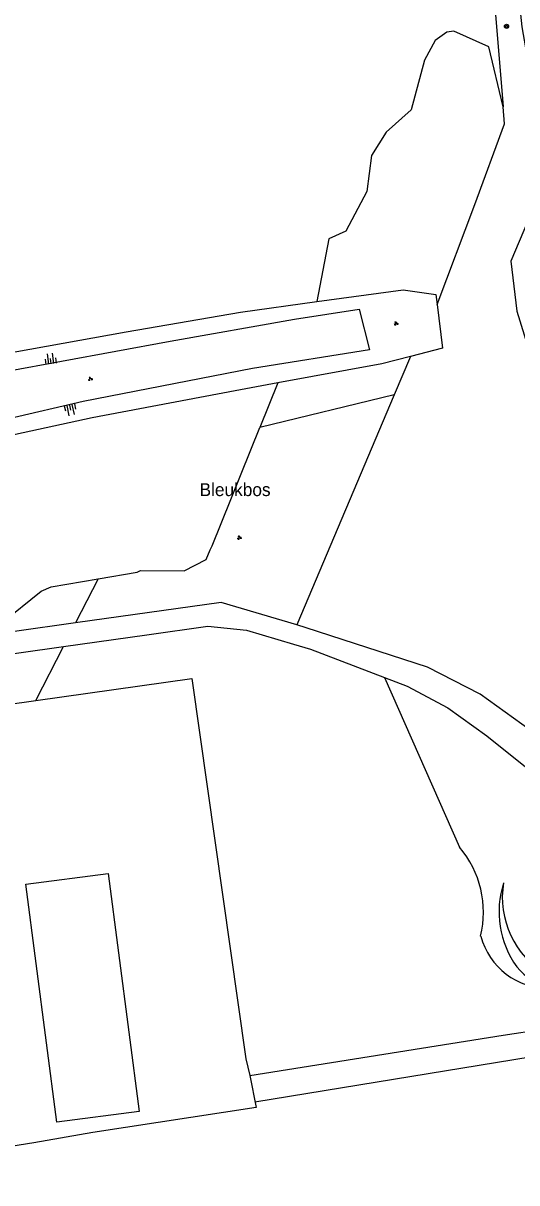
# Model space of a CAD drawing. Extents: x 125000 to 129004, y 397500 to 399008.
# Drawn here: x 126006.6 to 126102.2, y 397500 to 397724.5 of the extents above; entities that cross this region are included whole.
import ezdxf

# ---------------------------------------------------------------- set-up
doc = ezdxf.new("R2010")
doc.units = 0
for name, color, linetype in [('gg-afsc-lijn draadraster', 7, 'Continuous'), ('gg-anno-openbare ruimte label', 7, 'Continuous'), ('gg-knt-BGT kruinlijn', 7, 'Continuous'), ('gg-knt-bovenkant onderkant talud', 7, 'Continuous'), ('gg-knt-onverhard', 7, 'Continuous'), ('gt-bbg-plantopografie pand', 7, 'Continuous'), ('gt-grn-groengrens', 7, 'Continuous'), ('gt-symb-boom', 7, 'Continuous'), ('gt-symb-groenvak', 7, 'Continuous'), ('gt-symb-talud symbool', 7, 'Continuous'), ('gx-grn-maaiveld', 7, 'Continuous')]:
    doc.layers.add(name, color=color, linetype=linetype)

# ---------------------------------------------------------------- blocks, each defined once
blk = doc.blocks.new('gt0-BOOM')
at = {"layer": 'gt-symb-boom'}
for radius in [0.4, 0.2]:
    blk.add_circle((0, 0), radius, dxfattribs=at)
blk = doc.blocks.new('gt0-GRVAK')
at = {"layer": 'gt-symb-groenvak'}
for p, q in [((-0.11, 0.19), (-0.23, 0.24)), ((-0.18, 0.15), (0.09, 0.15)), ((-0.09, 0.21), (-0.16, 0.32)), ((-0.05, 0.21), (-0.05, 0.39)), ((0, 0.21), (0.06, 0.32)), ((0.01, 0.19), (0.13, 0.24)), ((0.26, -0.05), (0.2, 0.06)), ((0.3, -0.05), (0.3, 0.13)), ((0.35, -0.05), (0.41, 0.06)), ((-0.24, -0.23), (-0.36, -0.18)), ((-0.32, -0.26), (-0.05, -0.26)), ((-0.23, -0.21), (-0.29, -0.09)), ((-0.18, -0.2), (-0.18, -0.02)), ((-0.14, -0.21), (-0.07, -0.09)), ((-0.12, -0.23), (0, -0.18)), ((0.24, -0.07), (0.12, -0.02)), ((0.17, -0.11), (0.44, -0.11)), ((0.37, -0.07), (0.49, -0.02))]:
    blk.add_line(p, q, dxfattribs=at)
blk = doc.blocks.new('gt0-TALUD_1')
at = {"layer": 'gt-symb-talud symbool'}
for p, q in [((-1, -1), (-1, 0)), ((-0.5, -2), (-0.5, 0)), ((0, -1), (0, 0)), ((0.5, -2), (0.5, 0)), ((1, -1), (1, 0))]:
    blk.add_line(p, q, dxfattribs=at)

msp = doc.modelspace()

# ---------------------------------------------------------------- linework, layer by layer
at = {"layer": 'gg-afsc-lijn draadraster'}
msp.add_lwpolyline([(126051.46, 397515.7), (126198.71, 397539.74), (126267.59, 397550.89), (126278.2, 397500)], dxfattribs=at)
at = {"layer": 'gg-knt-BGT kruinlijn'}
msp.add_lwpolyline([(126073.67, 397661.32), (126051.03, 397657.69), (126018.21, 397651.29), (125989.35, 397644.55), (125967.38, 397640.9), (125969.88, 397652.16), (126003.49, 397657.14), (126035.06, 397662.99), (126059.15, 397667.23), (126071.66, 397669.17), (126073.67, 397661.32)], dxfattribs=at)
msp.add_arc((126116.64, 397555.22), 17.26, 170.3567, 239.7827, dxfattribs=at)
at = {"layer": 'gg-knt-bovenkant onderkant talud'}
for points in [[(126063.47, 397670.62), (126080.15, 397672.94), (126086.5, 397671.98), (126086.74, 397670.05)], [(125959.49, 397654.55), (125974.01, 397656.86), (125998.85, 397659.81), (126026.56, 397664.77), (126048.67, 397668.56), (126063.47, 397670.62)], [(126086.74, 397670.05), (126087.8, 397661.61), (126081.63, 397660.01)], [(126081.63, 397660.01), (126076.03, 397658.56), (126055.92, 397654.89)], [(126055.92, 397654.89), (126047.68, 397653.38), (126020, 397648.15), (125985.79, 397640.73), (125958.27, 397635.98), (125958.7, 397652.38)]]:
    msp.add_lwpolyline(points, dxfattribs=at)
for centre, radius, start, end in [((126117.1, 397552.49), 18.36, 162.1742, 215.642), ((126112.9, 397550.97), 14.11, 220.5741, 251.9124)]:
    msp.add_arc(centre, radius, start, end, dxfattribs=at)
at = {"layer": 'gg-knt-onverhard'}
for points in [[(126100, 397756.19), (126100.33, 397756.04), (126102.82, 397752.9), (126102.63, 397749.78), (126101.62, 397738.69), (126103.15, 397723.83), (126105.48, 397710.56), (126107.74, 397700.62), (126107.48, 397693.69), (126101.04, 397678.43), (126102.22, 397668.77), (126107.61, 397651.27), (126113.05, 397629.84), (126114.23, 397618.93), (126113.78, 397610.27), (126112.39, 397600.68), (126109.62, 397584.17), (126095.09, 397594.6), (126084.92, 397599.84), (126061.39, 397607.49), (126059.59, 397608.02)], [(126059.59, 397608.02), (126044.94, 397612.35), (126016.75, 397608.42)], [(126016.75, 397608.42), (126004.96, 397606.78), (125970.06, 397601.41), (125926.58, 397595.14)], [(126014.4, 397603.84), (126030.55, 397606.12), (126042.39, 397607.77), (126049.86, 397606.98), (126058.95, 397604.3)], [(125923.23, 397589.37), (125937.21, 397592.52), (125997.52, 397601.46), (126014.4, 397603.84)], [(126058.95, 397604.3), (126062.26, 397603.32), (126076.54, 397597.86)], [(126076.54, 397597.86), (126080.98, 397596.17), (126088.86, 397591.99), (126096.4, 397586.58), (126112.88, 397573.3), (126117.71, 397569.5), (126138.34, 397566.94), (126159.34, 397570.09), (126171, 397570.07), (126205.28, 397564.59)]]:
    msp.add_lwpolyline(points, dxfattribs=at)
at = {"layer": 'gt-bbg-plantopografie pand'}
msp.add_lwpolyline([(126007.15, 397557.8), (126023.07, 397559.88), (126029.06, 397513.81), (126013.15, 397511.74), (126007.15, 397557.8)], dxfattribs=at)
at = {"layer": 'gt-grn-groengrens'}
for p, q in [((126081.63, 397660.01), (126078.47, 397652.56)), ((126055.92, 397654.89), (126052.44, 397646.24)), ((126078.47, 397652.56), (126052.44, 397646.24)), ((126078.47, 397652.56), (126059.59, 397608.02)), ((126021.11, 397616.94), (126016.75, 397608.42)), ((126009.05, 397593.39), (126014.4, 397603.84)), ((126076.54, 397597.86), (126091.09, 397564.98))]:
    msp.add_line(p, q, dxfattribs=at)
for points in [[(126100, 397756.19), (126097.84, 397728.53), (126099.52, 397708.32)], [(126099.52, 397708.32), (126096.78, 397719.96), (126090.01, 397722.97), (126088.66, 397722.82), (126086.4, 397721.16), (126084.3, 397717.4), (126081.74, 397707.77), (126076.92, 397703.41), (126074.07, 397698.89), (126073.16, 397691.97), (126069.1, 397684.3), (126065.79, 397682.8), (126063.47, 397670.62)], [(126086.74, 397670.05), (126094.08, 397689.42), (126099.79, 397705.06), (126099.52, 397708.32)], [(126021.11, 397616.94), (126028.7, 397618.21), (126029.32, 397618.56), (126037.81, 397618.51), (126042.05, 397620.71), (126042.81, 397622.58), (126043.22, 397623.33), (126052.44, 397646.24)], [(125931.07, 397603.13), (125943.28, 397606.67), (125953.74, 397607.31), (125979.58, 397610.73), (125985.56, 397613.72), (125987.48, 397616.28), (125989.83, 397617.35), (125991.75, 397617.35), (125993.46, 397616.5), (125997.3, 397612.87), (125997.73, 397608.81), (126002.43, 397608.38), (126010.12, 397614.58), (126012.04, 397615.43), (126021.11, 397616.94)], [(125929.64, 397557.36), (125930.79, 397557.32), (125930.48, 397559.56), (125922.63, 397581.22), (126009.05, 397593.39)]]:
    msp.add_lwpolyline(points, dxfattribs=at)
for centre, radius, start, end in [((126076.2, 397552.35), 19.53, 346.4462, 40.3049), ((126108.6, 397551.46), 13.91, 195.3706, 269.6922)]:
    msp.add_arc(centre, radius, start, end, dxfattribs=at)
at = {"layer": 'gx-grn-maaiveld'}
for p, q in [((126099.56, 397528.56), (126137.65, 397534.62)), ((126050.48, 397520.76), (126099.56, 397528.56))]:
    msp.add_line(p, q, dxfattribs=at)
for points in [[(126009.05, 397593.39), (126039.29, 397597.63), (126049.74, 397524), (126050.48, 397520.76)], [(126050.48, 397520.76), (126051.72, 397514.59), (126020.09, 397509.71), (126008.7, 397507.76), (125990.41, 397504.83), (125973.9, 397502.88), (125949.75, 397500)]]:
    msp.add_lwpolyline(points, dxfattribs=at)

# ---------------------------------------------------------------- block references
at = {"layer": 'gt-symb-boom'}
msp.add_blockref('gt0-BOOM', (126100.2, 397723.92), dxfattribs=at)
at = {"layer": 'gt-symb-groenvak'}
for p in [(126078.8, 397666.4), (126019.59, 397655.65), (126048.47, 397624.92)]:
    msp.add_blockref('gt0-GRVAK', p, dxfattribs=at)
at = {"layer": 'gt-symb-talud symbool'}
for p, xscale, yscale, rotation in [((126011.99, 397658.6), 0.9998849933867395, 0.9998849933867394, -172.3561302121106), ((126015.62, 397650.6), 1.0002329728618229, 1.0002329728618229, 11.82670392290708)]:
    msp.add_blockref('gt0-TALUD_1', p, dxfattribs=dict(at, xscale=xscale, yscale=yscale, rotation=rotation))

# ---------------------------------------------------------------- texts
at = {"layer": 'gg-anno-openbare ruimte label'}
msp.add_text('Bleukbos', height=2.5, dxfattribs=at).set_placement((126040.76, 397632.97))

doc.saveas('drawing.dxf')
